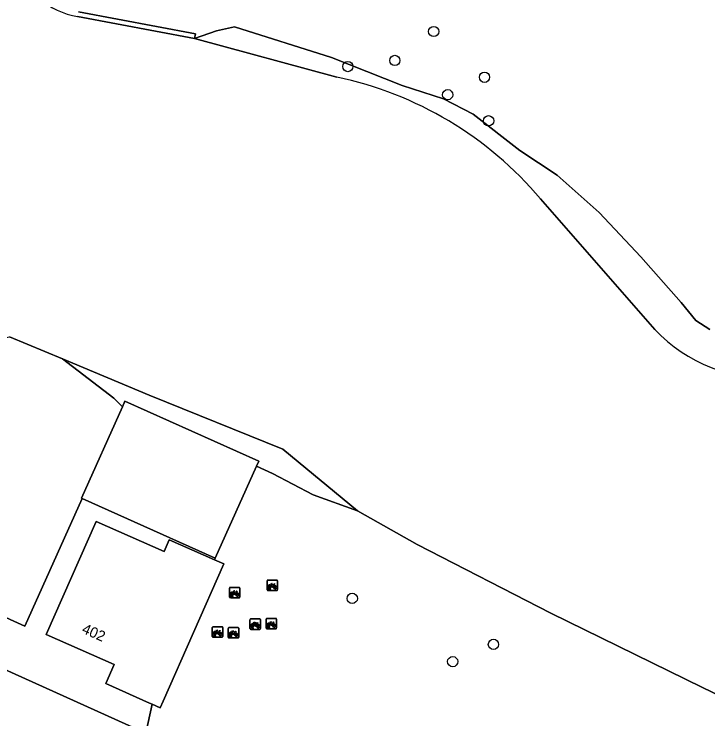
# Model space of a CAD drawing. Extents: x 155640 to 156811, y 382821 to 384049.
# Drawn here: x 155824.5 to 155890.7, y 383682.9 to 383750.2 of the extents above; entities that cross this region are included whole.
import ezdxf

# ---------------------------------------------------------------- set-up
doc = ezdxf.new("R2010")
doc.units = 0
for name, color, linetype in [('IMGEO_Boom', 7, 'Continuous'), ('IMGEO_Fietsenrek', 7, 'Continuous'), ('IMGEO_Groenvoorziening', 7, 'Continuous'), ('IMGEO_Kademuur', 7, 'Continuous'), ('IMGEO_Meer_plas_ven_vijver', 7, 'Continuous'), ('IMGEO_Oever', 7, 'Continuous'), ('IMGEO_Pand', 7, 'Continuous'), ('IMGEO_Pand_nummerreeks', 7, 'Continuous'), ('IMGEO_Rijbaan_lokaal_open', 7, 'Continuous'), ('IMGEO_Voetpad_halfverhard', 7, 'Continuous'), ('IMGEO_Voetpad_open', 7, 'Continuous')]:
    doc.layers.add(name, color=color, linetype=linetype)

msp = doc.modelspace()

# ---------------------------------------------------------------- linework, layer by layer
at = {"layer": 'IMGEO_Boom'}
for centre in [(155864.562, 383748.526), (155860.854, 383745.768), (155856.374, 383745.178), (155869.41, 383744.157), (155865.897, 383742.496), (155869.802, 383740.01), (155856.796, 383694.428), (155870.262, 383690.04), (155866.373, 383688.39)]:
    msp.add_circle(centre, 0.489, dxfattribs=at)
at = {"layer": 'IMGEO_Fietsenrek'}
for p, q in [((155848.667, 383695.251), (155848.667, 383696.092)), ((155848.667, 383696.092), (155848.667, 383695.251)), ((155848.742, 383696.176), (155849.583, 383696.176)), ((155849.583, 383696.176), (155848.742, 383696.176)), ((155849.354, 383695.725), (155849.39, 383695.63)), ((155849.667, 383696.101), (155849.667, 383695.26)), ((155849.667, 383695.26), (155849.667, 383696.101)), ((155845.079, 383694.552), (155845.079, 383695.393)), ((155845.079, 383695.393), (155845.079, 383694.552)), ((155845.154, 383695.477), (155845.995, 383695.477)), ((155845.995, 383695.477), (155845.154, 383695.477)), ((155845.766, 383695.026), (155845.802, 383694.931)), ((155846.079, 383695.402), (155846.079, 383694.561)), ((155846.079, 383694.561), (155846.079, 383695.402)), ((155849.592, 383695.176), (155848.751, 383695.176)), ((155848.751, 383695.176), (155849.592, 383695.176)), ((155848.794, 383695.26), (155848.833, 383695.42)), ((155848.828, 383695.26), (155848.794, 383695.26)), ((155848.863, 383695.408), (155848.828, 383695.26)), ((155848.905, 383695.432), (155848.904, 383695.436)), ((155848.946, 383695.26), (155848.912, 383695.402)), ((155848.936, 383695.443), (155848.937, 383695.436)), ((155848.944, 383695.406), (155848.979, 383695.26)), ((155848.979, 383695.26), (155848.946, 383695.26)), ((155846.004, 383694.477), (155845.163, 383694.477)), ((155845.163, 383694.477), (155846.004, 383694.477)), ((155845.206, 383694.561), (155845.245, 383694.721)), ((155845.24, 383694.561), (155845.206, 383694.561)), ((155845.275, 383694.709), (155845.24, 383694.561)), ((155845.317, 383694.733), (155845.316, 383694.737)), ((155845.358, 383694.561), (155845.324, 383694.703)), ((155845.348, 383694.744), (155845.349, 383694.737)), ((155845.356, 383694.707), (155845.391, 383694.561)), ((155845.391, 383694.561), (155845.358, 383694.561)), ((155847.037, 383691.547), (155847.037, 383692.388)), ((155847.037, 383692.388), (155847.037, 383691.547)), ((155847.112, 383692.472), (155847.953, 383692.472)), ((155847.953, 383692.472), (155847.112, 383692.472)), ((155848.037, 383692.397), (155848.037, 383691.556)), ((155848.037, 383691.556), (155848.037, 383692.397)), ((155848.579, 383691.593), (155848.579, 383692.434)), ((155848.579, 383692.434), (155848.579, 383691.593)), ((155848.654, 383692.518), (155849.495, 383692.518)), ((155849.495, 383692.518), (155848.654, 383692.518)), ((155849.579, 383692.443), (155849.579, 383691.602)), ((155849.579, 383691.602), (155849.579, 383692.443)), ((155843.443, 383690.794), (155843.443, 383691.635)), ((155843.443, 383691.635), (155843.443, 383690.794)), ((155843.518, 383691.719), (155844.359, 383691.719)), ((155844.359, 383691.719), (155843.518, 383691.719)), ((155844.443, 383691.644), (155844.443, 383690.803)), ((155844.443, 383690.803), (155844.443, 383691.644)), ((155844.963, 383690.725), (155844.963, 383691.566)), ((155844.963, 383691.566), (155844.963, 383690.725)), ((155845.038, 383691.65), (155845.879, 383691.65)), ((155845.879, 383691.65), (155845.038, 383691.65)), ((155845.963, 383691.575), (155845.963, 383690.734)), ((155845.963, 383690.734), (155845.963, 383691.575)), ((155847.164, 383691.556), (155847.203, 383691.716)), ((155847.198, 383691.556), (155847.164, 383691.556)), ((155847.233, 383691.704), (155847.198, 383691.556)), ((155847.275, 383691.728), (155847.274, 383691.732)), ((155847.316, 383691.556), (155847.282, 383691.698)), ((155847.306, 383691.739), (155847.307, 383691.732)), ((155847.314, 383691.702), (155847.349, 383691.556)), ((155847.349, 383691.556), (155847.316, 383691.556)), ((155847.724, 383692.021), (155847.76, 383691.926)), ((155849.504, 383691.518), (155848.663, 383691.518)), ((155848.663, 383691.518), (155849.504, 383691.518)), ((155848.706, 383691.602), (155848.745, 383691.762)), ((155848.74, 383691.602), (155848.706, 383691.602)), ((155848.775, 383691.75), (155848.74, 383691.602)), ((155848.817, 383691.774), (155848.816, 383691.778)), ((155848.858, 383691.602), (155848.824, 383691.744)), ((155848.848, 383691.785), (155848.849, 383691.778)), ((155848.856, 383691.748), (155848.891, 383691.602)), ((155848.891, 383691.602), (155848.858, 383691.602)), ((155849.266, 383692.067), (155849.302, 383691.972)), ((155843.57, 383690.803), (155843.609, 383690.963)), ((155843.639, 383690.951), (155843.604, 383690.803)), ((155843.681, 383690.975), (155843.68, 383690.979)), ((155843.722, 383690.803), (155843.688, 383690.945)), ((155843.712, 383690.986), (155843.713, 383690.979)), ((155843.72, 383690.949), (155843.755, 383690.803)), ((155844.13, 383691.268), (155844.166, 383691.173)), ((155845.09, 383690.734), (155845.129, 383690.894)), ((155845.159, 383690.882), (155845.124, 383690.734)), ((155845.201, 383690.906), (155845.2, 383690.91)), ((155845.242, 383690.734), (155845.208, 383690.876)), ((155845.232, 383690.917), (155845.233, 383690.91)), ((155845.24, 383690.88), (155845.275, 383690.734)), ((155845.65, 383691.199), (155845.686, 383691.104)), ((155847.962, 383691.472), (155847.121, 383691.472)), ((155847.121, 383691.472), (155847.962, 383691.472)), ((155844.368, 383690.719), (155843.527, 383690.719)), ((155843.527, 383690.719), (155844.368, 383690.719)), ((155843.604, 383690.803), (155843.57, 383690.803)), ((155843.755, 383690.803), (155843.722, 383690.803)), ((155845.888, 383690.65), (155845.047, 383690.65)), ((155845.047, 383690.65), (155845.888, 383690.65)), ((155845.124, 383690.734), (155845.09, 383690.734)), ((155845.275, 383690.734), (155845.242, 383690.734))]:
    msp.add_line(p, q, dxfattribs=at)
for points in [[(155849.001, 383695.65), (155848.949, 383695.56), (155848.909, 383695.535), (155848.91, 383695.582), (155848.965, 383695.676)], [(155848.98, 383695.702), (155849.075, 383695.866), (155849.161, 383695.852), (155849.163, 383695.843), (155849.107, 383695.832), (155849.08, 383695.787), (155849.336, 383695.746)], [(155849.276, 383695.458), (155849.226, 383695.458), (155849.035, 383695.709), (155849.016, 383695.677)], [(155849.323, 383695.721), (155849.066, 383695.762), (155849.049, 383695.733), (155849.216, 383695.513), (155849.323, 383695.721)], [(155849.371, 383695.623), (155849.341, 383695.7), (155849.232, 383695.482), (155849.275, 383695.482)], [(155849.305, 383695.482), (155849.425, 383695.481), (155849.381, 383695.595)], [(155849.401, 383695.602), (155849.456, 383695.457), (155849.306, 383695.457)], [(155849.336, 383695.746), (155849.361, 383695.795), (155849.355, 383695.799), (155849.332, 383695.803), (155849.32, 383695.81), (155849.319, 383695.813), (155849.321, 383695.818), (155849.416, 383695.803), (155849.418, 383695.793), (155849.408, 383695.78), (155849.396, 383695.774), (155849.382, 383695.78), (155849.354, 383695.725)], [(155845.413, 383694.951), (155845.361, 383694.861), (155845.321, 383694.836), (155845.322, 383694.883), (155845.377, 383694.977)], [(155845.392, 383695.003), (155845.487, 383695.167), (155845.573, 383695.153), (155845.575, 383695.144), (155845.519, 383695.133), (155845.492, 383695.088), (155845.748, 383695.047)], [(155845.688, 383694.759), (155845.638, 383694.759), (155845.447, 383695.01), (155845.428, 383694.978)], [(155845.735, 383695.022), (155845.478, 383695.063), (155845.461, 383695.034), (155845.628, 383694.814), (155845.735, 383695.022)], [(155845.783, 383694.924), (155845.753, 383695.001), (155845.644, 383694.783), (155845.687, 383694.783)], [(155845.717, 383694.783), (155845.837, 383694.782), (155845.793, 383694.896)], [(155845.813, 383694.903), (155845.868, 383694.758), (155845.718, 383694.758)], [(155845.748, 383695.047), (155845.773, 383695.096), (155845.767, 383695.1), (155845.744, 383695.104), (155845.732, 383695.111), (155845.731, 383695.114), (155845.733, 383695.119), (155845.828, 383695.104), (155845.83, 383695.094), (155845.82, 383695.081), (155845.808, 383695.075), (155845.794, 383695.081), (155845.766, 383695.026)], [(155848.892, 383692.044), (155848.987, 383692.208), (155849.073, 383692.194), (155849.075, 383692.185), (155849.019, 383692.174), (155848.992, 383692.129), (155849.248, 383692.088)], [(155847.371, 383691.946), (155847.319, 383691.856), (155847.279, 383691.831), (155847.28, 383691.878), (155847.335, 383691.972)], [(155847.35, 383691.998), (155847.445, 383692.162), (155847.531, 383692.148), (155847.533, 383692.139), (155847.477, 383692.128), (155847.45, 383692.083), (155847.706, 383692.042)], [(155847.646, 383691.754), (155847.596, 383691.754), (155847.405, 383692.005), (155847.386, 383691.973)], [(155847.693, 383692.017), (155847.436, 383692.058), (155847.419, 383692.029), (155847.586, 383691.809), (155847.693, 383692.017)], [(155847.741, 383691.919), (155847.711, 383691.996), (155847.602, 383691.778), (155847.645, 383691.778)], [(155847.675, 383691.778), (155847.795, 383691.777), (155847.751, 383691.891)], [(155847.771, 383691.898), (155847.826, 383691.753), (155847.676, 383691.753)], [(155847.706, 383692.042), (155847.731, 383692.091), (155847.725, 383692.095), (155847.702, 383692.099), (155847.69, 383692.106), (155847.689, 383692.109), (155847.691, 383692.114), (155847.786, 383692.099), (155847.788, 383692.089), (155847.778, 383692.076), (155847.766, 383692.07), (155847.752, 383692.076), (155847.724, 383692.021)], [(155848.913, 383691.992), (155848.861, 383691.902), (155848.821, 383691.877), (155848.822, 383691.924), (155848.877, 383692.018)], [(155849.188, 383691.8), (155849.138, 383691.8), (155848.947, 383692.051), (155848.928, 383692.019)], [(155849.235, 383692.063), (155848.978, 383692.104), (155848.961, 383692.075), (155849.128, 383691.855), (155849.235, 383692.063)], [(155849.283, 383691.965), (155849.253, 383692.042), (155849.144, 383691.824), (155849.187, 383691.824)], [(155849.217, 383691.824), (155849.337, 383691.823), (155849.293, 383691.937)], [(155849.313, 383691.944), (155849.368, 383691.799), (155849.218, 383691.799)], [(155849.248, 383692.088), (155849.273, 383692.137), (155849.267, 383692.141), (155849.244, 383692.145), (155849.232, 383692.152), (155849.231, 383692.155), (155849.233, 383692.16), (155849.328, 383692.145), (155849.33, 383692.135), (155849.32, 383692.122), (155849.308, 383692.116), (155849.294, 383692.122), (155849.266, 383692.067)], [(155843.777, 383691.193), (155843.725, 383691.103), (155843.685, 383691.078), (155843.686, 383691.125), (155843.741, 383691.219)], [(155843.756, 383691.245), (155843.851, 383691.409), (155843.937, 383691.395), (155843.939, 383691.386), (155843.883, 383691.375), (155843.856, 383691.33), (155844.112, 383691.289)], [(155844.052, 383691.001), (155844.002, 383691.001), (155843.811, 383691.252), (155843.792, 383691.22)], [(155844.099, 383691.264), (155843.842, 383691.305), (155843.825, 383691.276), (155843.992, 383691.056), (155844.099, 383691.264)], [(155844.147, 383691.166), (155844.117, 383691.243), (155844.008, 383691.025), (155844.051, 383691.025)], [(155844.081, 383691.025), (155844.201, 383691.024), (155844.157, 383691.138)], [(155844.177, 383691.145), (155844.232, 383691), (155844.082, 383691)], [(155844.112, 383691.289), (155844.137, 383691.338), (155844.131, 383691.342), (155844.108, 383691.346), (155844.096, 383691.353), (155844.095, 383691.356), (155844.097, 383691.361), (155844.192, 383691.346), (155844.194, 383691.336), (155844.184, 383691.323), (155844.172, 383691.317), (155844.158, 383691.323), (155844.13, 383691.268)], [(155845.297, 383691.124), (155845.245, 383691.034), (155845.205, 383691.009), (155845.206, 383691.056), (155845.261, 383691.15)], [(155845.276, 383691.176), (155845.371, 383691.34), (155845.457, 383691.326), (155845.459, 383691.317), (155845.403, 383691.306), (155845.376, 383691.261), (155845.632, 383691.22)], [(155845.572, 383690.932), (155845.522, 383690.932), (155845.331, 383691.183), (155845.312, 383691.151)], [(155845.619, 383691.195), (155845.362, 383691.236), (155845.345, 383691.207), (155845.512, 383690.987), (155845.619, 383691.195)], [(155845.667, 383691.097), (155845.637, 383691.174), (155845.528, 383690.956), (155845.571, 383690.956)], [(155845.601, 383690.956), (155845.721, 383690.955), (155845.677, 383691.069)], [(155845.697, 383691.076), (155845.752, 383690.931), (155845.602, 383690.931)], [(155845.632, 383691.22), (155845.657, 383691.269), (155845.651, 383691.273), (155845.628, 383691.277), (155845.616, 383691.284), (155845.615, 383691.287), (155845.617, 383691.292), (155845.712, 383691.277), (155845.714, 383691.267), (155845.704, 383691.254), (155845.692, 383691.248), (155845.678, 383691.254), (155845.65, 383691.199)]]:
    msp.add_lwpolyline(points, dxfattribs=at)
for centre, radius, start, end in [((155848.745, 383696.098), 0.0779, 92.4484, 184.28452), ((155848.745, 383696.098), 0.0779, 92.4484, 184.28452), ((155848.907, 383695.561), 0.159, 62.67661, 242.13685), ((155848.907, 383695.561), 0.129, 63.31916, 238.90302), ((155848.907, 383695.561), 0.129, 283.60429, 43.43025), ((155848.907, 383695.561), 0.159, 283.5766, 46.60424), ((155849.434, 383695.477), 0.159, 113.3408, 178.32165), ((155849.434, 383695.477), 0.159, 187.0065, 105.77075), ((155849.434, 383695.477), 0.129, 113.92302, 177.95563), ((155849.434, 383695.477), 0.129, 188.67146, 104.58832), ((155849.589, 383696.098), 0.0779, 2.4484, 94.28452), ((155849.589, 383696.098), 0.0779, 2.4484, 94.28452), ((155845.157, 383695.399), 0.0779, 92.4484, 184.28452), ((155845.157, 383695.399), 0.0779, 92.4484, 184.28452), ((155845.319, 383694.862), 0.159, 62.67661, 242.13685), ((155845.319, 383694.862), 0.129, 63.31916, 238.90302), ((155845.319, 383694.862), 0.129, 283.60429, 43.43025), ((155845.319, 383694.862), 0.159, 283.5766, 46.60424), ((155845.846, 383694.778), 0.159, 113.3408, 178.32165), ((155845.846, 383694.778), 0.159, 187.0065, 105.77075), ((155845.846, 383694.778), 0.129, 113.92302, 177.95563), ((155845.846, 383694.778), 0.129, 188.67146, 104.58832), ((155846.001, 383695.399), 0.0779, 2.4484, 94.28452), ((155846.001, 383695.399), 0.0779, 2.4484, 94.28452), ((155848.745, 383695.254), 0.0779, 182.4484, 274.28452), ((155848.745, 383695.254), 0.0779, 182.4484, 274.28452), ((155848.887, 383695.432), 0.0499, 12.8025, 158.69338), ((155848.907, 383695.561), 0.159, 253.99666, 271.78671), ((155848.887, 383695.432), 0.0174, 12.8025, 163.45023), ((155848.907, 383695.561), 0.129, 253.41502, 269.02044), ((155849.589, 383695.254), 0.0779, 272.4484, 4.28452), ((155849.589, 383695.254), 0.0779, 272.4484, 4.28452), ((155845.157, 383694.555), 0.0779, 182.4484, 274.28452), ((155845.157, 383694.555), 0.0779, 182.4484, 274.28452), ((155845.299, 383694.733), 0.0499, 12.8025, 158.69338), ((155845.319, 383694.862), 0.159, 253.99666, 271.78671), ((155845.299, 383694.733), 0.0174, 12.8025, 163.45023), ((155845.319, 383694.862), 0.129, 253.41502, 269.02044), ((155846.001, 383694.555), 0.0779, 272.4484, 4.28452), ((155846.001, 383694.555), 0.0779, 272.4484, 4.28452), ((155847.115, 383692.394), 0.0779, 92.4484, 184.28452), ((155847.115, 383692.394), 0.0779, 92.4484, 184.28452), ((155847.959, 383692.394), 0.0779, 2.4484, 94.28452), ((155847.959, 383692.394), 0.0779, 2.4484, 94.28452), ((155848.657, 383692.44), 0.0779, 92.4484, 184.28452), ((155848.657, 383692.44), 0.0779, 92.4484, 184.28452), ((155849.501, 383692.44), 0.0779, 2.4484, 94.28452), ((155849.501, 383692.44), 0.0779, 2.4484, 94.28452), ((155843.521, 383691.641), 0.0779, 92.4484, 184.28452), ((155843.521, 383691.641), 0.0779, 92.4484, 184.28452), ((155844.365, 383691.641), 0.0779, 2.4484, 94.28452), ((155844.365, 383691.641), 0.0779, 2.4484, 94.28452), ((155845.041, 383691.572), 0.0779, 92.4484, 184.28452), ((155845.041, 383691.572), 0.0779, 92.4484, 184.28452), ((155845.885, 383691.572), 0.0779, 2.4484, 94.28452), ((155845.885, 383691.572), 0.0779, 2.4484, 94.28452), ((155847.115, 383691.55), 0.0779, 182.4484, 274.28452), ((155847.115, 383691.55), 0.0779, 182.4484, 274.28452), ((155847.277, 383691.857), 0.159, 62.67661, 242.13685), ((155847.277, 383691.857), 0.129, 63.31916, 238.90302), ((155847.257, 383691.728), 0.0499, 12.8025, 158.69338), ((155847.277, 383691.857), 0.159, 253.99666, 271.78671), ((155847.257, 383691.728), 0.0174, 12.8025, 163.45023), ((155847.277, 383691.857), 0.129, 253.41502, 269.02044), ((155847.277, 383691.857), 0.129, 283.60429, 43.43025), ((155847.277, 383691.857), 0.159, 283.5766, 46.60424), ((155847.804, 383691.773), 0.159, 113.3408, 178.32165), ((155847.804, 383691.773), 0.159, 187.0065, 105.77075), ((155847.804, 383691.773), 0.129, 113.92302, 177.95563), ((155847.804, 383691.773), 0.129, 188.67146, 104.58832), ((155847.959, 383691.55), 0.0779, 272.4484, 4.28452), ((155847.959, 383691.55), 0.0779, 272.4484, 4.28452), ((155848.657, 383691.596), 0.0779, 182.4484, 274.28452), ((155848.657, 383691.596), 0.0779, 182.4484, 274.28452), ((155848.819, 383691.903), 0.159, 62.67661, 242.13685), ((155848.819, 383691.903), 0.129, 63.31916, 238.90302), ((155848.799, 383691.774), 0.0499, 12.8025, 158.69338), ((155848.819, 383691.903), 0.159, 253.99666, 271.78671), ((155848.799, 383691.774), 0.0174, 12.8025, 163.45023), ((155848.819, 383691.903), 0.129, 253.41502, 269.02044), ((155848.819, 383691.903), 0.129, 283.60429, 43.43025), ((155848.819, 383691.903), 0.159, 283.5766, 46.60424), ((155849.346, 383691.819), 0.159, 113.3408, 178.32165), ((155849.346, 383691.819), 0.159, 187.0065, 105.77075), ((155849.346, 383691.819), 0.129, 113.92302, 177.95563), ((155849.346, 383691.819), 0.129, 188.67146, 104.58832), ((155849.501, 383691.596), 0.0779, 272.4484, 4.28452), ((155849.501, 383691.596), 0.0779, 272.4484, 4.28452), ((155843.683, 383691.104), 0.159, 62.67661, 242.13685), ((155843.683, 383691.104), 0.129, 63.31916, 238.90302), ((155843.663, 383690.975), 0.0499, 12.8025, 158.69338), ((155843.683, 383691.104), 0.159, 253.99666, 271.78671), ((155843.663, 383690.975), 0.0174, 12.8025, 163.45023), ((155843.683, 383691.104), 0.129, 253.41502, 269.02044), ((155843.683, 383691.104), 0.129, 283.60429, 43.43025), ((155843.683, 383691.104), 0.159, 283.5766, 46.60424), ((155844.21, 383691.02), 0.159, 113.3408, 178.32165), ((155844.21, 383691.02), 0.159, 187.0065, 105.77075), ((155844.21, 383691.02), 0.129, 113.92302, 177.95563), ((155844.21, 383691.02), 0.129, 188.67146, 104.58832), ((155845.203, 383691.035), 0.159, 62.67661, 242.13685), ((155845.203, 383691.035), 0.129, 63.31916, 238.90302), ((155845.183, 383690.906), 0.0499, 12.8025, 158.69338), ((155845.203, 383691.035), 0.159, 253.99666, 271.78671), ((155845.183, 383690.906), 0.0174, 12.8025, 163.45023), ((155845.203, 383691.035), 0.129, 253.41502, 269.02044), ((155845.203, 383691.035), 0.129, 283.60429, 43.43025), ((155845.203, 383691.035), 0.159, 283.5766, 46.60424), ((155845.73, 383690.951), 0.159, 113.3408, 178.32165), ((155845.73, 383690.951), 0.159, 187.0065, 105.77075), ((155845.73, 383690.951), 0.129, 113.92302, 177.95563), ((155845.73, 383690.951), 0.129, 188.67146, 104.58832), ((155843.521, 383690.797), 0.0779, 182.4484, 274.28452), ((155843.521, 383690.797), 0.0779, 182.4484, 274.28452), ((155844.365, 383690.797), 0.0779, 272.4484, 4.28452), ((155844.365, 383690.797), 0.0779, 272.4484, 4.28452), ((155845.041, 383690.728), 0.0779, 182.4484, 274.28452), ((155845.041, 383690.728), 0.0779, 182.4484, 274.28452), ((155845.885, 383690.728), 0.0779, 272.4484, 4.28452), ((155845.885, 383690.728), 0.0779, 272.4484, 4.28452)]:
    msp.add_arc(centre, radius, start, end, dxfattribs=at)
at = {"layer": 'IMGEO_Groenvoorziening'}
for points in [[(155830.677, 383750.395), (155841.838, 383748.314), (155841.756, 383747.872), (155843.854, 383748.588), (155845.563, 383748.973), (155854.814, 383746.051), (155861.562, 383743.371), (155865.494, 383742.11), (155868.318, 383740.625), (155872.78, 383737.16), (155876.334, 383734.824), (155880.334, 383731.265), (155884.314, 383727.037), (155888.179, 383722.677), (155889.566, 383720.942), (155890.916, 383720.102)], [(155817.64, 383695.365), (155825.556, 383691.789), (155831.019, 383703.945), (155830.95, 383703.976), (155834.869, 383712.698), (155834.06, 383713.546), (155829.139, 383717.292), (155824.091, 383719.401)], [(155862.997, 383699.57), (155857.284, 383702.786), (155853.055, 383704.321), (155849.173, 383706.345), (155847.664, 383707.031), (155843.714, 383698.272), (155843.645, 383698.119), (155844.535, 383697.729), (155838.757, 383684.617), (155838.475, 383683.977), (155837.691, 383684.328), (155837.091, 383681.558), (155837.008, 383681.173)], [(155868.931, 383679.876), (155877.692, 383676.77), (155881.355, 383675.105), (155890.307, 383670.527), (155902.497, 383664), (155902.876, 383665.102), (155904.225, 383667.039), (155905.683, 383669.302), (155907.189, 383672.181), (155907.88, 383674.096), (155908.272, 383675.968), (155908.272, 383677.186), (155907.706, 383678.013), (155903.311, 383679.624), (155890.195, 383685.908), (155875.724, 383693.004), (155862.997, 383699.57)]]:
    msp.add_lwpolyline(points, dxfattribs=at)
msp.add_arc((155858.565, 383682.107), 79.235, 58.84869, 67.81009, dxfattribs=at)
at = {"layer": 'IMGEO_Kademuur'}
msp.add_lwpolyline([(155830.595, 383749.953), (155841.756, 383747.872), (155841.838, 383748.314), (155830.677, 383750.395)], dxfattribs=at)
msp.add_arc((155831.871, 383757.406), 7.562, 199.09111, 260.28757, dxfattribs=at)
at = {"layer": 'IMGEO_Meer_plas_ven_vijver'}
for points in [[(155824.725, 383754.933), (155823.463, 383758.043), (155820.517, 383757.206), (155820.34, 383757.855), (155816.915, 383756.827), (155817.068, 383756.296), (155813.673, 383755.134), (155812.528, 383750.515), (155809.771, 383748.352), (155805.459, 383726.633), (155809.44, 383724.673), (155823.109, 383719.189), (155824.091, 383719.401), (155829.139, 383717.292), (155837.409, 383713.836), (155850.173, 383708.673), (155857.284, 383702.786), (155862.997, 383699.57), (155875.724, 383693.004), (155890.195, 383685.908), (155903.311, 383679.624)], [(155855.314, 383744.182), (155841.756, 383747.872), (155830.595, 383749.953)], [(155885.654, 383720.087), (155874.761, 383732.549)]]:
    msp.add_lwpolyline(points, dxfattribs=at)
for centre, radius, start, end in [((155831.871, 383757.406), 7.562, 199.09111, 260.28757), ((155848.072, 383710.005), 34.936, 40.1882, 78.03692), ((155896.424, 383730.257), 14.812, 223.35918, 273.91938)]:
    msp.add_arc(centre, radius, start, end, dxfattribs=at)
at = {"layer": 'IMGEO_Oever'}
for points in [[(155890.916, 383720.102), (155889.566, 383720.942), (155888.179, 383722.677), (155884.314, 383727.037), (155880.334, 383731.265), (155876.334, 383734.824), (155872.78, 383737.16), (155868.318, 383740.625), (155865.494, 383742.11), (155861.562, 383743.371), (155854.814, 383746.051), (155845.563, 383748.973), (155843.854, 383748.588), (155841.756, 383747.872)], [(155841.756, 383747.872), (155855.314, 383744.182)], [(155874.761, 383732.549), (155885.654, 383720.087)]]:
    msp.add_lwpolyline(points, dxfattribs=at)
msp.add_lwpolyline([(155837.409, 383713.836), (155829.139, 383717.292), (155834.06, 383713.546), (155834.869, 383712.698), (155835.114, 383713.244), (155847.889, 383707.531), (155847.664, 383707.031), (155849.173, 383706.345), (155853.055, 383704.321), (155857.284, 383702.786), (155850.173, 383708.673)], close=True, dxfattribs=at)
for centre, radius, start, end in [((155848.072, 383710.005), 34.936, 40.1882, 78.03692), ((155896.424, 383730.257), 14.812, 223.35918, 273.91938)]:
    msp.add_arc(centre, radius, start, end, dxfattribs=at)
at = {"layer": 'IMGEO_Pand'}
msp.add_lwpolyline([(155844.535, 383697.729), (155843.645, 383698.119), (155839.334, 383700.007), (155838.845, 383698.901), (155832.353, 383701.769), (155827.599, 383690.994), (155834.085, 383688.128), (155833.278, 383686.301), (155837.446, 383684.437), (155837.691, 383684.328), (155838.475, 383683.977), (155838.757, 383684.617)], close=True, dxfattribs=at)
at = {"layer": 'IMGEO_Rijbaan_lokaal_open'}
msp.add_lwpolyline([(155828.926, 383658.93), (155833.177, 383677.945), (155836.101, 383677.265), (155836.188, 383677.652), (155837.008, 383681.173), (155837.091, 383681.558), (155815.726, 383691.188), (155815.343, 383690.352), (155814.314, 383688.134), (155813.593, 383686.61), (155824.346, 383673.654)], dxfattribs=at)
at = {"layer": 'IMGEO_Voetpad_halfverhard'}
msp.add_arc((155858.565, 383682.107), 79.235, 58.84869, 67.81009, dxfattribs=at)
at = {"layer": 'IMGEO_Voetpad_open'}
for points in [[(155847.664, 383707.031), (155847.889, 383707.531), (155835.114, 383713.244), (155834.869, 383712.698), (155830.95, 383703.976), (155831.019, 383703.945), (155843.714, 383698.272)], [(155815.726, 383691.188), (155837.091, 383681.558), (155837.691, 383684.328), (155837.446, 383684.437), (155833.278, 383686.301), (155834.085, 383688.128), (155827.599, 383690.994), (155832.353, 383701.769), (155838.845, 383698.901), (155839.334, 383700.007), (155843.645, 383698.119), (155843.714, 383698.272), (155831.019, 383703.945), (155825.556, 383691.789), (155817.64, 383695.365)]]:
    msp.add_lwpolyline(points, close=True, dxfattribs=at)

# ---------------------------------------------------------------- texts
at = {"layer": 'IMGEO_Pand_nummerreeks'}
msp.add_text('402', height=1, rotation=336.15923, dxfattribs=at).set_placement((155830.923, 383691.165))

doc.saveas('drawing.dxf')
